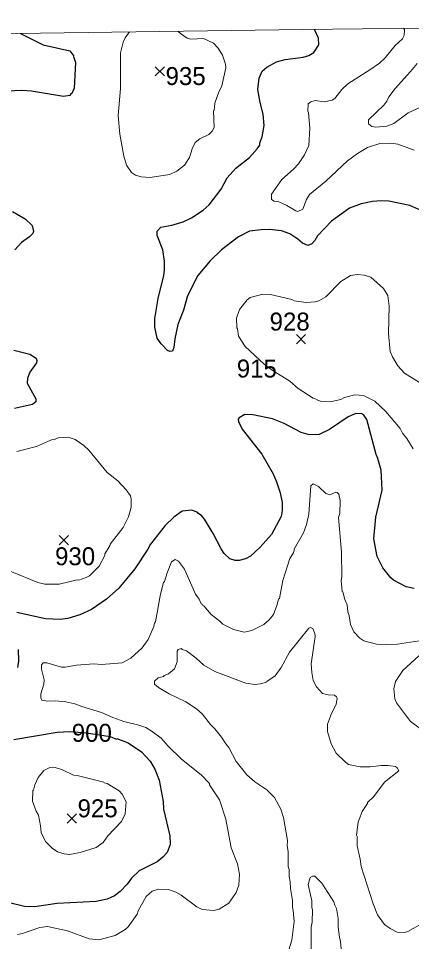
# Model space of a CAD drawing. Extents: x 265.7 to 292.1, y 7676.2 to 7704.2.
# Drawn here: x 271.891 to 273.642, y 7699.898 to 7704.012 of the extents above; entities that cross this region are included whole.
import ezdxf
from ezdxf.enums import TextEntityAlignment as Align

# ---------------------------------------------------------------- set-up
doc = ezdxf.new("R2010")
doc.units = 0
doc.header["$LTSCALE"] = 0.032
for name, color, linetype, lineweight in [('1', 7, 'Continuous', 25), ('2', 7, 'Continuous', 13), ('21', 7, 'Continuous', 25), ('63', 7, 'Continuous', 25)]:
    doc.layers.add(name, color=color, linetype=linetype, lineweight=lineweight)
doc.layers.add('61', color=7, linetype='Continuous')

msp = doc.modelspace()

# ---------------------------------------------------------------- linework, layer by layer
at = {"layer": '1'}
for points in [[(273.2859, 7703.1083), (273.2229, 7703.0437), (273.2109, 7703.0221), (273.1982, 7703.0077), (273.1806, 7703.0005), (273.1559, 7703.0109), (273.1359, 7703.0285), (273.0992, 7703.0524), (273.0633, 7703.066), (273.0099, 7703.0716), (272.9715, 7703.0708), (272.9205, 7703.0644), (272.871, 7703.0397), (272.7952, 7702.9806), (272.7449, 7702.9327), (272.6907, 7702.8673), (272.6444, 7702.7755), (272.626, 7702.7117), (272.6005, 7702.6479), (272.5869, 7702.584), (272.5837, 7702.5457), (272.5765, 7702.529), (272.5646, 7702.5274), (272.555, 7702.5329), (272.5263, 7702.5617), (272.5095, 7702.5872), (272.4983, 7702.6367), (272.4991, 7702.675), (272.5135, 7702.7644), (272.539, 7702.8665), (272.5422, 7702.892), (272.5414, 7702.9303), (272.5343, 7702.9814), (272.5087, 7703.0453), (272.5087, 7703.0644), (272.5247, 7703.0827), (272.5742, 7703.0915), (272.6252, 7703.1059), (272.6611, 7703.1234), (272.7138, 7703.1577), (272.7401, 7703.1817), (272.7936, 7703.2511), (272.8207, 7703.3022), (272.8598, 7703.3445), (272.9205, 7703.3923), (272.9548, 7703.4307), (272.966, 7703.4482), (272.9667, 7703.4586), (272.9771, 7703.4841), (272.9859, 7703.5352), (272.9811, 7703.5863), (272.9675, 7703.6373), (272.9572, 7703.6956), (272.9636, 7703.7467), (272.9771, 7703.7778), (272.9971, 7703.7945), (273.0402, 7703.8185), (273.0785, 7703.8296), (273.1599, 7703.84), (273.1838, 7703.8472), (273.2061, 7703.8608), (273.2285, 7703.8951), (273.2269, 7703.9246), (273.2096, 7703.9633)], [(271.9006, 7703.9456), (272.0012, 7703.8943), (272.1201, 7703.8679), (272.1377, 7703.8448), (272.1361, 7703.8424), (272.1448, 7703.8161), (272.1385, 7703.7012), (272.1289, 7703.678), (272.1241, 7703.6764), (272.1193, 7703.6692), (272.0922, 7703.6645), (271.9486, 7703.6884), (271.9055, 7703.6908), (271.8065, 7703.6868)], [(273.6339, 7703.1785), (273.5405, 7703.1984), (273.5062, 7703.2), (273.4679, 7703.1969), (273.4168, 7703.1857), (273.3657, 7703.1665), (273.2859, 7703.1083)], [(271.864, 7703.1522), (271.9214, 7703.1194), (271.9517, 7703.0899), (271.9581, 7703.0628), (271.9549, 7703.0532), (271.9406, 7703.0389), (271.9047, 7703.0133), (271.8751, 7702.9806)], [(273.6873, 7703.1554), (273.6339, 7703.1785)], [(271.8704, 7702.5337), (271.9422, 7702.5154), (271.9693, 7702.4978), (271.9733, 7702.4875), (271.9717, 7702.4779), (271.9422, 7702.4356), (271.931, 7702.4093), (271.9294, 7702.3861), (271.9677, 7702.3175), (271.9677, 7702.3031), (271.9533, 7702.2912), (271.8736, 7702.2736)], [(273.653, 7701.4717), (273.6179, 7701.4788), (273.562, 7701.5084), (273.5493, 7701.5187), (273.5142, 7701.5642), (273.4894, 7701.6137), (273.4743, 7701.6935), (273.483, 7701.7893), (273.511, 7701.9105), (273.507, 7701.9983), (273.4918, 7702.051), (273.4838, 7702.0685), (273.4423, 7702.2249), (273.4296, 7702.2449), (273.4208, 7702.2497), (273.3945, 7702.2513), (273.3594, 7702.2369), (273.2772, 7702.181), (273.2301, 7702.1587), (273.2141, 7702.1563), (273.1822, 7702.1587), (273.1503, 7702.1667), (273.0753, 7702.2066), (273.0226, 7702.2273), (272.9348, 7702.2457), (272.8997, 7702.2473), (272.8734, 7702.2321), (272.8702, 7702.2257), (272.8718, 7702.2154), (272.8878, 7702.1811), (272.9755, 7702.0701), (273.0258, 7701.9824), (273.041, 7701.9473), (273.0569, 7701.8978), (273.0657, 7701.8547), (273.0657, 7701.8196), (273.0609, 7701.7924), (273.0178, 7701.7118), (272.9683, 7701.656), (272.9253, 7701.6153), (272.9029, 7701.6033), (272.8742, 7701.5961), (272.8566, 7701.5969), (272.8327, 7701.6033), (272.808, 7701.6281), (272.7936, 7701.648), (272.7577, 7701.7174), (272.7194, 7701.7813), (272.7058, 7701.7964), (272.6899, 7701.8076), (272.6875, 7701.8124), (272.6619, 7701.8204), (272.6204, 7701.8164), (272.5837, 7701.7892), (272.5446, 7701.7517), (272.4792, 7701.6688), (272.468, 7701.6472), (272.4098, 7701.5594), (272.3379, 7701.4733), (272.2837, 7701.4246), (272.2159, 7701.3783), (272.164, 7701.3544), (272.1113, 7701.3384), (272.0762, 7701.3328), (272.0108, 7701.336), (271.8831, 7701.3647)], [(271.8895, 7701.2004), (271.8919, 7701.1477), (271.8863, 7701.1198)], [(271.8704, 7700.7982), (272.0635, 7700.8309)], [(272.0635, 7700.8309), (272.1206, 7700.8346), (272.1941, 7700.829), (272.2997, 7700.812), (272.328, 7700.8007), (272.3292, 7700.803), (272.3795, 7700.783)], [(272.3795, 7700.783), (272.4385, 7700.7439), (272.4784, 7700.7016), (272.4991, 7700.6665), (272.5183, 7700.6179), (272.535, 7700.5221), (272.5366, 7700.4886), (272.5646, 7700.3689), (272.5662, 7700.3306), (272.5534, 7700.2947), (272.5343, 7700.2739), (272.5087, 7700.254), (272.4281, 7700.2125), (272.3946, 7700.1806), (272.3755, 7700.1542), (272.3443, 7700.1215), (272.3188, 7700.1016), (272.2869, 7700.0864), (272.2374, 7700.0768), (272.0635, 7700.0672), (271.9629, 7700.0529), (271.9182, 7700.0545), (271.8512, 7700.0712)]]:
    msp.add_lwpolyline(points, dxfattribs=at)
at = {"layer": '2'}
for points in [[(273.6064, 7703.9687), (273.61, 7703.9618), (273.6095, 7703.9358), (273.601, 7703.9213), (273.5692, 7703.8911), (273.5237, 7703.8368), (273.4998, 7703.8137), (273.4559, 7703.7826), (273.3578, 7703.7211), (273.3314, 7703.6956), (273.2995, 7703.6549), (273.2891, 7703.6477), (273.2524, 7703.6405), (273.2125, 7703.6461), (273.1934, 7703.6413), (273.1822, 7703.6318), (273.1798, 7703.599), (273.183, 7703.5911), (273.1886, 7703.524), (273.1838, 7703.4466), (273.1654, 7703.4043), (273.1391, 7703.3644), (273.1168, 7703.3405), (273.0641, 7703.295), (273.0178, 7703.2288), (273.0186, 7703.2048), (273.0306, 7703.1977), (273.0513, 7703.1945), (273.0865, 7703.1793), (273.1264, 7703.1546), (273.1351, 7703.1522), (273.1583, 7703.1625), (273.1742, 7703.2048), (273.1878, 7703.2272), (273.2596, 7703.287), (273.357, 7703.3772), (273.4016, 7703.4099), (273.4463, 7703.437), (273.5014, 7703.4546), (273.5493, 7703.4562), (273.5812, 7703.4514), (273.653, 7703.4259)], [(272.3859, 7703.9521), (272.3659, 7703.9254), (272.3571, 7703.907), (272.3451, 7703.8592), (272.3459, 7703.6996), (272.3348, 7703.5799), (272.342, 7703.4969), (272.3611, 7703.3979), (272.3723, 7703.3581), (272.3946, 7703.3261), (272.413, 7703.3142), (272.4369, 7703.307), (272.4768, 7703.3038), (272.5646, 7703.3173), (272.5965, 7703.3317), (272.63, 7703.358), (272.6524, 7703.3924), (272.6651, 7703.4315), (272.6779, 7703.4594), (272.6994, 7703.4753), (272.7393, 7703.4953), (272.7537, 7703.5097), (272.7633, 7703.5264), (272.7601, 7703.6006), (272.7625, 7703.6022), (272.7657, 7703.6341), (272.7816, 7703.6804), (272.7968, 7703.7123), (272.8143, 7703.7921), (272.8127, 7703.8081), (272.7992, 7703.848), (272.78, 7703.8799), (272.7601, 7703.9023), (272.7146, 7703.923), (272.6587, 7703.9198), (272.6421, 7703.9241), (272.6121, 7703.9449), (272.6012, 7703.9551)], [(273.6674, 7703.8121), (273.6378, 7703.7754), (273.5684, 7703.7004), (273.5405, 7703.6629), (273.5317, 7703.6437), (273.5181, 7703.6254), (273.4495, 7703.5607), (273.4503, 7703.5432), (273.4655, 7703.5304), (273.4822, 7703.528), (273.5317, 7703.5328), (273.5636, 7703.544), (273.6275, 7703.5918), (273.6817, 7703.6174)], [(273.6769, 7702.3901), (273.6107, 7702.4316), (273.5812, 7702.4643), (273.5564, 7702.5042), (273.5469, 7702.5282), (273.5397, 7702.608), (273.5429, 7702.7293), (273.5357, 7702.7771), (273.5173, 7702.8091), (273.4599, 7702.8585), (273.4312, 7702.8681), (273.3993, 7702.8713), (273.3697, 7702.8665), (273.3274, 7702.8402), (273.2596, 7702.7715), (273.2285, 7702.754), (273.2125, 7702.7492), (273.1726, 7702.7468), (273.1192, 7702.754), (273.1088, 7702.7604), (273.013, 7702.7819), (272.9795, 7702.7835), (272.9237, 7702.7691), (272.9093, 7702.7588), (272.875, 7702.7149), (272.8622, 7702.6766), (272.863, 7702.6335), (272.867, 7702.6287), (272.8718, 7702.5968), (272.9005, 7702.5505), (272.9854, 7702.4714), (273.0209, 7702.4451), (273.1, 7702.3957), (273.1375, 7702.363), (273.203, 7702.3199), (273.2221, 7702.3135), (273.2237, 7702.3103), (273.2365, 7702.3071), (273.2859, 7702.3047), (273.3274, 7702.3143), (273.3426, 7702.3223), (273.3897, 7702.3351), (273.428, 7702.3311), (273.4782, 7702.3071), (273.5277, 7702.2601), (273.5908, 7702.185), (273.6011, 7702.1643), (273.6203, 7702.1404), (273.6498, 7702.0941)], [(271.8831, 7702.0821), (271.9717, 7702.1044), (272.0387, 7702.1348), (272.0523, 7702.1364), (272.0683, 7702.1428), (272.1129, 7702.1459), (272.1433, 7702.1364), (272.1816, 7702.1092), (272.2039, 7702.0885), (272.2861, 7701.9879), (272.3332, 7701.952), (272.3715, 7701.9121), (272.3898, 7701.8842), (272.3938, 7701.8707), (272.3938, 7701.8347), (272.381, 7701.7909), (272.3579, 7701.743), (272.2989, 7701.6696), (272.2973, 7701.6616), (272.2765, 7701.6265), (272.2757, 7701.6185), (272.2502, 7701.5706), (272.2071, 7701.5283), (272.1927, 7701.5203), (272.16, 7701.5092), (272.152, 7701.5108), (272.073, 7701.4916), (272.0092, 7701.4916), (271.9773, 7701.498), (271.8544, 7701.5483)], [(272.1496, 7701.1293), (272.2263, 7701.1365), (272.2614, 7701.1325), (272.3523, 7701.1397), (272.3922, 7701.1605), (272.4425, 7701.2075), (272.4688, 7701.2442), (272.4944, 7701.3025), (272.4968, 7701.3177), (272.5015, 7701.3224), (272.5239, 7701.4461), (272.5374, 7701.4988), (272.5422, 7701.5028), (272.5534, 7701.5419), (272.5734, 7701.5898), (272.5893, 7701.6009), (272.6045, 7701.5937), (272.6308, 7701.5579), (272.6803, 7701.4461), (272.6962, 7701.4238), (272.705, 7701.403), (272.7098, 7701.4022), (272.7114, 7701.3967), (272.717, 7701.3943), (272.7489, 7701.3552), (272.788, 7701.3264), (272.8008, 7701.3129), (272.8487, 7701.2889), (272.8965, 7701.277), (272.9301, 7701.2841), (272.9843, 7701.3113), (273.0075, 7701.332), (273.0266, 7701.356), (273.0426, 7701.3951), (273.0497, 7701.4238), (273.0537, 7701.427), (273.0681, 7701.5068), (273.0992, 7701.6057), (273.116, 7701.6313), (273.1208, 7701.6504), (273.1607, 7701.719), (273.1734, 7701.7573), (273.1838, 7701.8036), (273.1926, 7701.9297), (273.203, 7701.9377), (273.2269, 7701.9265), (273.2596, 7701.8946), (273.278, 7701.8898), (273.3051, 7701.901), (273.3099, 7701.9002), (273.3179, 7701.8914), (273.3242, 7701.8643), (273.3218, 7701.8052), (273.3171, 7701.7877), (273.3298, 7701.6329), (273.3314, 7701.5243), (273.329, 7701.5068), (273.333, 7701.4589), (273.3362, 7701.4573), (273.345, 7701.4222), (273.3554, 7701.3983), (273.3578, 7701.3671), (273.3641, 7701.3504), (273.3697, 7701.3105), (273.3849, 7701.2786), (273.4112, 7701.2498), (273.4296, 7701.2379), (273.4854, 7701.2235), (273.5301, 7701.2211), (273.5796, 7701.2235), (273.6754, 7701.2387)], [(273.092, 7700.2987), (273.088, 7700.3242), (273.0896, 7700.3481), (273.0721, 7700.4503), (273.0601, 7700.4886), (273.0322, 7700.5397), (272.9971, 7700.5748), (272.9444, 7700.6099), (272.9085, 7700.641), (272.8614, 7700.7008), (272.8279, 7700.7631), (272.8143, 7700.779), (272.796, 7700.8094), (272.7657, 7700.8461), (272.7457, 7700.8652), (272.709, 7700.9123), (272.6843, 7700.9354), (272.6364, 7700.9666), (272.563, 7701.0017), (272.5151, 7701.0304), (272.4976, 7701.0448), (272.4968, 7701.0583), (272.5127, 7701.0735), (272.5367, 7701.0791), (272.5406, 7701.0839), (272.5598, 7701.0918), (272.5861, 7701.1142), (272.5973, 7701.1445), (272.5981, 7701.1924), (272.6029, 7701.2004), (272.618, 7701.2036), (272.6204, 7701.1996), (272.6388, 7701.1932), (272.6827, 7701.1613), (272.7162, 7701.1301), (272.7657, 7701.1014), (272.9045, 7701.0495), (272.9444, 7701.044), (272.9684, 7701.0464), (272.9955, 7701.0535), (272.9971, 7701.0575), (273.0346, 7701.0831), (273.0617, 7701.1198), (273.0976, 7701.1876), (273.1838, 7701.2953), (273.1902, 7701.2977), (273.2022, 7701.2937), (273.2117, 7701.2706), (273.2133, 7701.2578), (273.195, 7701.1365), (273.1974, 7701.0966), (273.2037, 7701.0615), (273.2181, 7701.0328), (273.246, 7701.0033), (273.27, 7700.9977), (273.2987, 7700.9969), (273.3083, 7700.9889), (273.3107, 7700.9825), (273.3067, 7700.9546), (273.2859, 7700.9147), (273.2676, 7700.8668), (273.2676, 7700.8349), (273.2835, 7700.779), (273.3067, 7700.7375), (273.3474, 7700.6976), (273.3617, 7700.6873), (273.4136, 7700.6761), (273.4583, 7700.6769), (273.5062, 7700.6833), (273.5381, 7700.6833), (273.57, 7700.6777), (273.578, 7700.6729), (273.586, 7700.6585), (273.5213, 7700.6091), (273.4735, 7700.5444), (273.4455, 7700.5173), (273.4455, 7700.5133), (273.4216, 7700.4774), (273.404, 7700.4295), (273.3969, 7700.3721), (273.4, 7700.3657), (273.3993, 7700.3242), (273.4136, 7700.2652), (273.4176, 7700.2332), (273.4703, 7700.0657), (273.491, 7700.0178), (273.5213, 7699.9747), (273.5461, 7699.9555), (273.578, 7699.9404), (273.6099, 7699.938), (273.6259, 7699.9428), (273.7097, 7699.9899)], [(273.6738, 7701.1716), (273.6035, 7701.1054), (273.5708, 7701.0567), (273.5636, 7701.0248), (273.5668, 7700.9801), (273.5748, 7700.9626), (273.6378, 7700.8788), (273.6801, 7700.8477)], [(271.994, 7701.1126), (271.994, 7701.1317), (272.0012, 7701.1397), (272.0172, 7701.1405), (272.0826, 7701.1206), (272.0986, 7701.1206), (272.1496, 7701.1293)], [(271.8863, 7699.93), (271.9087, 7699.9332), (271.9869, 7699.9611), (272.0204, 7699.9651), (272.1097, 7699.9452), (272.2055, 7699.9101), (272.2486, 7699.9061), (272.322, 7699.9244), (272.3659, 7699.9515), (272.3803, 7699.9643), (272.4202, 7700.0194), (272.4249, 7700.0353), (272.46, 7700.0992), (272.4864, 7700.1223), (272.5151, 7700.1319), (272.5598, 7700.1295), (272.5917, 7700.1183), (272.6157, 7700.1048), (272.6859, 7700.0529), (272.7098, 7700.0409), (272.7609, 7700.0369), (272.7848, 7700.0417), (272.8287, 7700.0696), (272.8606, 7700.1167), (272.8726, 7700.1487), (272.875, 7700.1965), (272.867, 7700.2444), (272.8383, 7700.3162), (272.8151, 7700.4439), (272.7872, 7700.5301), (272.7425, 7700.5963), (272.7417, 7700.6027), (272.7042, 7700.6418), (272.618, 7700.7104), (272.5574, 7700.7695), (272.5263, 7700.8046), (272.4872, 7700.8341), (272.4577, 7700.8516), (272.4273, 7700.8628), (272.3603, 7700.8788), (272.3108, 7700.8963), (272.2614, 7700.9195), (272.1736, 7700.945), (272.1417, 7700.9578), (272.1018, 7700.9666), (272.0539, 7700.9705), (272.022, 7700.9697), (271.9956, 7700.9745), (271.9901, 7700.9849), (271.9901, 7701.0025), (272.0036, 7701.0456), (272.0052, 7701.0647), (271.994, 7701.1126)], [(273.112, 7700.0816), (273.1024, 7700.1343), (273.1016, 7700.1646), (273.0968, 7700.1885), (273.0968, 7700.2197), (273.0928, 7700.2332), (273.092, 7700.2987)], [(273.1982, 7700.0505), (273.1974, 7700.08), (273.1822, 7700.1518), (273.191, 7700.1838), (273.2014, 7700.1901), (273.2109, 7700.1893), (273.242, 7700.1582), (273.2963, 7700.0744), (273.2995, 7700.0601), (273.3075, 7700.0449), (273.3147, 7700.0002), (273.3147, 7699.9619), (273.3203, 7699.9172), (273.3258, 7699.8981), (273.3282, 7699.8662)], [(273.0729, 7699.7896), (273.108, 7699.9045), (273.1184, 7699.9875), (273.1152, 7700.0369), (273.1112, 7700.0513), (273.112, 7700.0816)], [(273.2069, 7699.6842), (273.2045, 7699.7928), (273.1942, 7699.8694), (273.1942, 7699.9619), (273.199, 7699.9843), (273.2014, 7700.0401), (273.1982, 7700.0505)]]:
    msp.add_lwpolyline(points, dxfattribs=at)
msp.add_lwpolyline([(272.1369, 7700.6394), (272.1528, 7700.6386), (272.2717, 7700.6091), (272.2725, 7700.6051), (272.2861, 7700.6027), (272.3396, 7700.57), (272.3531, 7700.5548), (272.3707, 7700.5205), (272.3667, 7700.4678), (272.3499, 7700.4327), (272.2885, 7700.3697), (272.2677, 7700.3402), (272.2366, 7700.317), (272.1656, 7700.2947), (272.1177, 7700.2859), (272.0946, 7700.2883), (272.0651, 7700.2979), (272.0411, 7700.3138), (272.0116, 7700.3441), (271.9916, 7700.3848), (271.9893, 7700.4136), (271.9797, 7700.4615), (271.9701, 7700.479), (271.9541, 7700.5237), (271.9557, 7700.5724), (271.9581, 7700.5732), (271.9637, 7700.5971), (271.9781, 7700.629), (272.0036, 7700.6609), (272.0284, 7700.6721), (272.0539, 7700.6737), (272.0874, 7700.6633)], close=True, dxfattribs=at)
at = {"layer": '21'}
for p, q in [((272.4996, 7703.7974), (272.5408, 7703.7562)), ((272.5408, 7703.7974), (272.4996, 7703.7562)), ((273.1291, 7702.6037), (273.1703, 7702.5625)), ((273.1703, 7702.6037), (273.1291, 7702.5625)), ((272.0727, 7701.7077), (272.1139, 7701.6665)), ((272.1139, 7701.7077), (272.0727, 7701.6665)), ((272.108, 7700.467), (272.1492, 7700.4258)), ((272.1492, 7700.467), (272.108, 7700.4258))]:
    msp.add_line(p, q, dxfattribs=at)
at = {"layer": '63', "lineweight": 13}
msp.add_lwpolyline([(265.7179, 7703.8606), (266.2494, 7703.868), (266.7808, 7703.8754), (267.3123, 7703.8828), (267.8437, 7703.8901), (268.3752, 7703.8974), (268.9066, 7703.9047), (269.4381, 7703.912), (269.9695, 7703.9193), (270.501, 7703.9265), (271.0324, 7703.9338), (271.5639, 7703.941), (272.0953, 7703.9482), (272.6268, 7703.9554), (273.1582, 7703.9626), (273.6896, 7703.9697), (274.2211, 7703.9769), (274.7525, 7703.984), (275.2839, 7703.9911), (275.8154, 7703.9982), (276.3468, 7704.0052), (276.8782, 7704.0123)], dxfattribs=at)

# ---------------------------------------------------------------- texts
at = {"layer": '61'}
for s, p in [('935', (272.6356, 7703.7156)), ('928', (273.099, 7702.6213)), ('915', (272.9527, 7702.412)), ('930', (272.1433, 7701.5753)), ('900', (272.2179, 7700.7883)), ('925', (272.2436, 7700.4519))]:
    msp.add_text(s, height=0.08, dxfattribs=at).set_placement(p, align=Align.CENTER)

doc.saveas('drawing.dxf')
